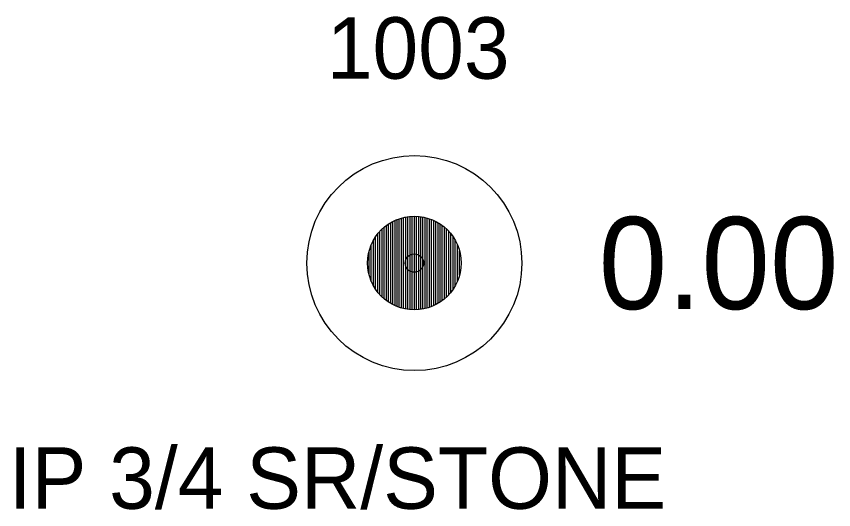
# Model space of a CAD drawing. Extents: x 1538847 to 1546108, y 887169 to 888935.
# Drawn here: x 1542422.21 to 1542435.51, y 888678.88 to 888686.9 of the extents above; entities that cross this region are included whole.
import ezdxf

# ---------------------------------------------------------------- set-up
doc = ezdxf.new("R2010")
doc.units = 0
for name, color, linetype in [('RD_EX_DV_Prop_txCode', 7, 'Continuous'), ('RD_EX_DV_PropPin', 7, 'Continuous'), ('RD_EX_TX_DV_Prop_ELEV', 7, 'Continuous'), ('RD_SMD_Locator', 7, 'Continuous')]:
    doc.layers.add(name, color=color, linetype=linetype)

msp = doc.modelspace()

# ---------------------------------------------------------------- linework, layer by layer
at = {"layer": 'RD_EX_DV_PropPin'}
for p, q in [((1542428.339, 888682.214), (1542428.339, 888683.565)), ((1542428.374, 888682.197), (1542428.374, 888683.582)), ((1542428.409, 888682.182), (1542428.409, 888683.597)), ((1542428.444, 888682.169), (1542428.444, 888683.61)), ((1542428.479, 888682.158), (1542428.479, 888683.621)), ((1542428.514, 888682.149), (1542428.514, 888683.63)), ((1542428.549, 888682.141), (1542428.549, 888683.637)), ((1542428.584, 888682.136), (1542428.584, 888683.643)), ((1542428.619, 888682.132), (1542428.619, 888683.647)), ((1542428.654, 888682.129), (1542428.654, 888683.65)), ((1542428.689, 888682.128), (1542428.689, 888683.65)), ((1542428.724, 888682.129), (1542428.724, 888683.65)), ((1542428.759, 888682.132), (1542428.759, 888683.647)), ((1542428.794, 888682.136), (1542428.794, 888683.643)), ((1542428.829, 888682.141), (1542428.829, 888683.637)), ((1542428.864, 888682.149), (1542428.864, 888683.63)), ((1542428.899, 888682.158), (1542428.899, 888683.621)), ((1542428.934, 888682.169), (1542428.934, 888683.61)), ((1542428.969, 888682.182), (1542428.969, 888683.597)), ((1542429.004, 888682.197), (1542429.004, 888683.582)), ((1542429.039, 888682.214), (1542429.039, 888683.565)), ((1542428.163, 888682.339), (1542428.163, 888683.44)), ((1542428.198, 888682.307), (1542428.198, 888683.472)), ((1542428.233, 888682.28), (1542428.233, 888683.499)), ((1542428.269, 888682.255), (1542428.269, 888683.524)), ((1542428.304, 888682.233), (1542428.304, 888683.546)), ((1542429.074, 888682.233), (1542429.074, 888683.546)), ((1542429.109, 888682.255), (1542429.109, 888683.524)), ((1542429.144, 888682.28), (1542429.144, 888683.499)), ((1542429.179, 888682.307), (1542429.179, 888683.472)), ((1542429.214, 888682.339), (1542429.214, 888683.44)), ((1542428.058, 888682.463), (1542428.058, 888683.316)), ((1542428.093, 888682.415), (1542428.093, 888683.364)), ((1542428.128, 888682.374), (1542428.128, 888683.404)), ((1542429.249, 888682.374), (1542429.249, 888683.404)), ((1542429.284, 888682.415), (1542429.284, 888683.364)), ((1542429.319, 888682.463), (1542429.319, 888683.316)), ((1542427.988, 888682.591), (1542427.988, 888683.187)), ((1542428.023, 888682.52), (1542428.023, 888683.259)), ((1542429.354, 888682.52), (1542429.354, 888683.259)), ((1542429.389, 888682.591), (1542429.389, 888683.187)), ((1542427.953, 888682.693), (1542427.953, 888683.086)), ((1542429.424, 888682.693), (1542429.424, 888683.086))]:
    msp.add_line(p, q, dxfattribs=at)
for radius in [1.75, 0.761]:
    msp.add_circle((1542428.689, 888682.889), radius, dxfattribs=at)
at = {"layer": 'RD_SMD_Locator'}
msp.add_circle((1542428.689, 888682.889), 0.15, dxfattribs=at)

# ---------------------------------------------------------------- texts
at = {"layer": 'RD_EX_DV_Prop_txCode'}
for s, p in [('1003', (1542427.264, 888685.889)), ('IP 3/4 SR/STONE', (1542422.086, 888678.889))]:
    msp.add_text(s, height=1, dxfattribs=at).set_placement(p)
at = {"layer": 'RD_EX_TX_DV_Prop_ELEV'}
msp.add_text('0.00', height=1.5, dxfattribs=at).set_placement((1542431.689, 888682.139))

doc.saveas('drawing.dxf')
